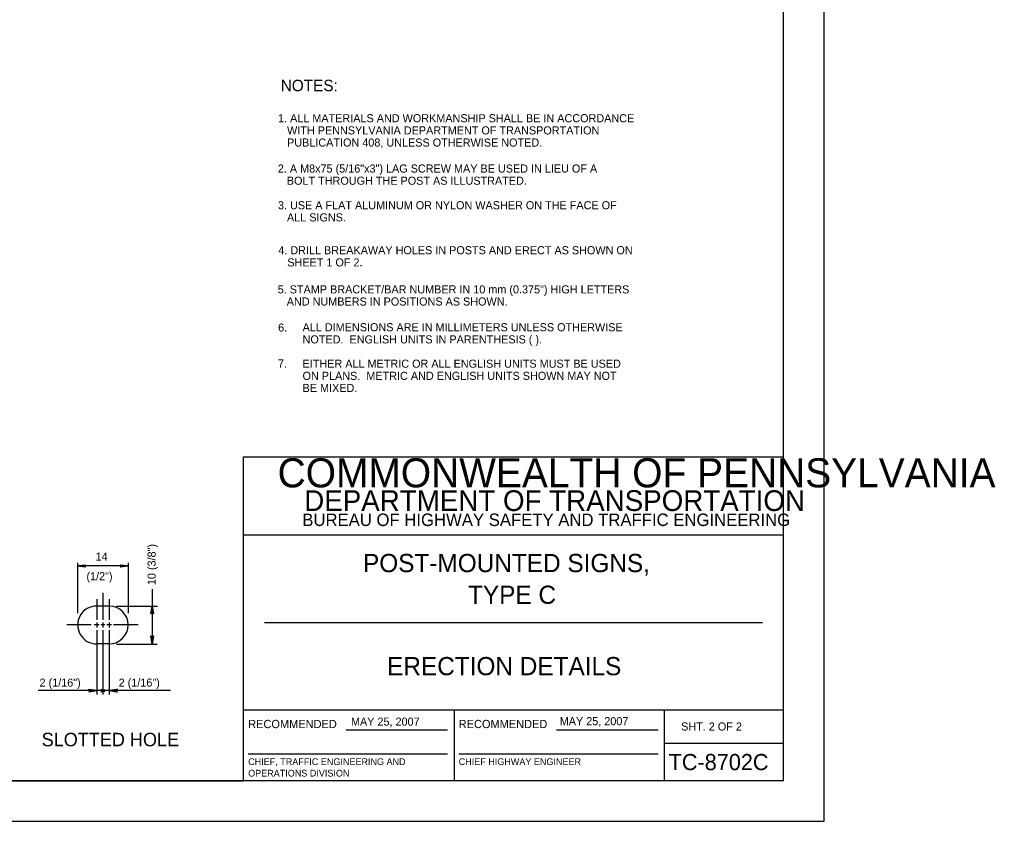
# Model space of a CAD drawing. Extents: x 649454 to 651200, y 295188 to 295782.
# Drawn here: x 650838.3 to 651199.9, y 295187.6 to 295484.6 of the extents above; entities that cross this region are included whole.
import ezdxf

# ---------------------------------------------------------------- set-up
doc = ezdxf.new("R2010")
doc.units = 0
for name, color, linetype in [('1', 7, 'Continuous'), ('2', 7, 'Continuous'), ('3', 7, 'Continuous'), ('PLT-BNDY', 7, 'Continuous')]:
    doc.layers.add(name, color=color, linetype=linetype)

msp = doc.modelspace()

# ---------------------------------------------------------------- linework, layer by layer
at = {"layer": '1'}
for p, q in [((651121.31, 295202.63), (651121.31, 295766.63)), ((650921.31, 295202.63), (650921.31, 295322.63)), ((650921.31, 295322.63), (651121.31, 295322.63)), ((651121.31, 295293.63), (650921.31, 295293.63)), ((650929.06, 295261.31), (651113.56, 295261.31)), ((650921.31, 295229), (651121.31, 295229)), ((650999.31, 295229), (650999.31, 295202.63)), ((651077.19, 295202.63), (651077.19, 295229)), ((650959.24, 295221.57), (650996.87, 295221.57)), ((651037.24, 295221.57), (651074.87, 295221.57)), ((651077.19, 295216.63), (651121.31, 295216.63)), ((650922.99, 295212.68), (650996.87, 295212.68)), ((651000.99, 295212.68), (651074.87, 295212.68)), ((651121.31, 295202.63), (650335.31, 295202.63)), ((650335.31, 295202.63), (650921.31, 295202.63))]:
    msp.add_line(p, q, dxfattribs=at)
at = {"layer": '2'}
for p, q in [((650871.52, 295267.42), (650866.85, 295267.42)), ((650871.52, 295253.41), (650866.9, 295253.41))]:
    msp.add_line(p, q, dxfattribs=at)
for centre, start, end in [((650866.85, 295260.41), 90, 270.4112), ((650871.52, 295260.41), 270, 90)]:
    msp.add_arc(centre, 7.01, start, end, dxfattribs=at)
at = {"layer": '3'}
for p, q in [((650859.77, 295283.42), (650859.77, 295264.73)), ((650878.52, 295282.3), (650859.77, 295282.3)), ((650878.52, 295283.42), (650878.52, 295264.73)), ((650869.15, 295272.36), (650869.15, 295262.36)), ((650887.4, 295273.64), (650887.4, 295253.35)), ((650866.9, 295269.98), (650866.9, 295262.36)), ((650871.52, 295269.98), (650871.52, 295262.36)), ((650874.27, 295267.39), (650889.4, 295267.39)), ((650864.77, 295260.48), (650855.77, 295260.48)), ((650867.77, 295260.48), (650865.9, 295260.48)), ((650866.9, 295261.36), (650866.9, 295259.48)), ((650869.9, 295260.48), (650868.52, 295260.48)), ((650869.15, 295261.36), (650869.15, 295259.48)), ((650872.4, 295260.48), (650870.65, 295260.48)), ((650871.52, 295261.36), (650871.52, 295259.48)), ((650882.27, 295260.48), (650873.15, 295260.48)), ((650866.9, 295258.48), (650866.9, 295234.7)), ((650869.15, 295258.48), (650869.15, 295234.7)), ((650871.52, 295258.48), (650871.52, 295234.7)), ((650874.27, 295253.35), (650889.27, 295253.35)), ((650866.9, 295236.08), (650845.21, 295236.08)), ((650871.52, 295236.08), (650866.9, 295236.08)), ((650868.4, 295235.58), (650869.9, 295236.45)), ((650869.9, 295235.58), (650868.4, 295236.45)), ((650894.22, 295236.08), (650871.52, 295236.08))]:
    msp.add_line(p, q, dxfattribs=at)
for points in [[(650862.65, 295281.92), (650862.52, 295282.05), (650859.77, 295282.3), (650862.65, 295281.92), (650862.77, 295281.8), (650859.77, 295282.3), (650862.52, 295282.42), (650862.65, 295282.55), (650859.77, 295282.3), (650862.77, 295282.67), (650862.65, 295282.55)], [(650875.65, 295282.55), (650875.77, 295282.42), (650878.52, 295282.3), (650875.65, 295282.55), (650875.52, 295282.67), (650878.52, 295282.3), (650875.77, 295282.17), (650875.65, 295281.92), (650878.52, 295282.3), (650875.52, 295281.8), (650875.65, 295281.92)], [(650887.02, 295264.64), (650887.27, 295264.77), (650887.4, 295267.39), (650887.02, 295264.64), (650886.9, 295264.52), (650887.4, 295267.39), (650887.65, 295264.77), (650887.77, 295264.64), (650887.4, 295267.39), (650887.9, 295264.52), (650887.77, 295264.64)], [(650887.77, 295256.22), (650887.65, 295256.1), (650887.4, 295253.35), (650887.77, 295256.22), (650887.9, 295256.35), (650887.4, 295253.35), (650887.27, 295256.1), (650887.15, 295256.22), (650887.4, 295253.35), (650886.9, 295256.35), (650887.15, 295256.22)], [(650864.02, 295236.45), (650864.15, 295236.2), (650866.9, 295236.08), (650864.02, 295236.45), (650863.9, 295236.58), (650866.9, 295236.08), (650864.15, 295235.95), (650864.02, 295235.7), (650866.9, 295236.08), (650863.9, 295235.58), (650864.02, 295235.7)], [(650874.27, 295235.7), (650874.27, 295235.95), (650871.52, 295236.08), (650874.27, 295235.7), (650874.52, 295235.58), (650871.52, 295236.08), (650874.27, 295236.2), (650874.27, 295236.45), (650871.52, 295236.08), (650874.52, 295236.58), (650874.27, 295236.45)]]:
    msp.add_lwpolyline(points, dxfattribs=at)
at = {"layer": 'PLT-BNDY'}
msp.add_lwpolyline([(650295.31, 295781.63), (651136.31, 295781.63), (651136.31, 295187.63), (650295.31, 295187.63)], close=True, dxfattribs=at)

# ---------------------------------------------------------------- texts
at = {"layer": '1'}
for s, height, p in [('COMMONWEALTH OF PENNSYLVANIA', 10.7828, (650933.9, 295311.36)), ('DEPARTMENT OF TRANSPORTATION', 7.6837, (650943.76, 295302.61)), ('BUREAU OF HIGHWAY SAFETY AND TRAFFIC ENGINEERING', 4.6253, (650943.04, 295297.04)), ('POST-MOUNTED SIGNS,', 6.75, (650965.54, 295279.97)), ('TYPE C', 6.75, (651004.45, 295268.22)), ('ERECTION DETAILS', 6.75, (650974.47, 295241.78)), ('RECOMMENDED', 3.048, (650922.99, 295222.2)), ('RECOMMENDED', 3.048, (651000.99, 295222.2)), ('SHT. 2 OF 2', 3, (651083.4, 295221.31)), ('CHIEF, TRAFFIC ENGINEERING AND', 2.5, (650922.99, 295208.51)), ('CHIEF HIGHWAY ENGINEER', 2.5, (651000.99, 295208.51)), ('TC-8702C', 6, (651078.77, 295206.63)), ('OPERATIONS DIVISION', 2.5, (650922.99, 295204.26))]:
    msp.add_text(s, height=height, dxfattribs=at).set_placement(p)
at = {"layer": '2'}
for s, height, p in [('MAY 25, 2007', 3, (650961.08, 295223.1)), ('MAY 25, 2007', 3, (651038.43, 295223.27)), ('SLOTTED HOLE', 5, (650846.49, 295215.47))]:
    msp.add_text(s, height=height, dxfattribs=at).set_placement(p)
at = {"layer": '3'}
for s, height, p in [('NOTES:', 4.25, (650935.05, 295458.07)), ('1. ALL MATERIALS AND WORKMANSHIP SHALL BE IN ACCORDANCE', 3, (650934.06, 295446.57)), ('   WITH PENNSYLVANIA DEPARTMENT OF TRANSPORTATION', 3, (650934.06, 295442.07)), ('   PUBLICATION 408, UNLESS OTHERWISE NOTED.', 3, (650934.06, 295437.57)), ('2. A M8x75 (5/16"x3") LAG SCREW MAY BE USED IN LIEU OF A', 3, (650933.97, 295427.94)), ('   BOLT THROUGH THE POST AS ILLUSTRATED.', 3, (650933.97, 295423.44)), ('3. USE A FLAT ALUMINUM OR NYLON WASHER ON THE FACE OF', 3, (650934.03, 295414.35)), ('   ALL SIGNS.', 3, (650934.03, 295409.85)), ('4. DRILL BREAKAWAY HOLES IN POSTS AND ERECT AS SHOWN ON', 3, (650934.14, 295397.69)), ('   SHEET 1 OF 2.', 3, (650934.14, 295393.19)), ('5. STAMP BRACKET/BAR NUMBER IN 10 mm (0.375") HIGH LETTERS ', 3, (650933.94, 295383.19)), ('   AND NUMBERS IN POSITIONS AS SHOWN.', 3, (650933.94, 295378.69)), ('6.', 3, (650934.1, 295369.05)), ('ALL DIMENSIONS ARE IN MILLIMETERS UNLESS OTHERWISE', 3, (650943.15, 295369.17)), ('NOTED.  ENGLISH UNITS IN PARENTHESIS ( ).', 3, (650943.15, 295364.67)), ('7.', 3, (650934.02, 295355.74)), ('EITHER ALL METRIC OR ALL ENGLISH UNITS MUST BE USED', 3, (650943.15, 295355.67)), ('ON PLANS.  METRIC AND ENGLISH UNITS SHOWN MAY NOT ', 3, (650943.15, 295351.17)), ('BE MIXED.', 3, (650943.15, 295346.67)), ('14 ', 3, (650866.46, 295284.22)), ('(1/2")', 3, (650863.08, 295276.95)), ('2 (1/16")', 3, (650845.69, 295237.55)), ('2 (1/16")', 3, (650875.01, 295237.55))]:
    msp.add_text(s, height=height, dxfattribs=at).set_placement(p)
msp.add_text('10 (3/8")', height=3, rotation=90, dxfattribs=at).set_placement((650888.72, 295275.15))

doc.saveas('drawing.dxf')
